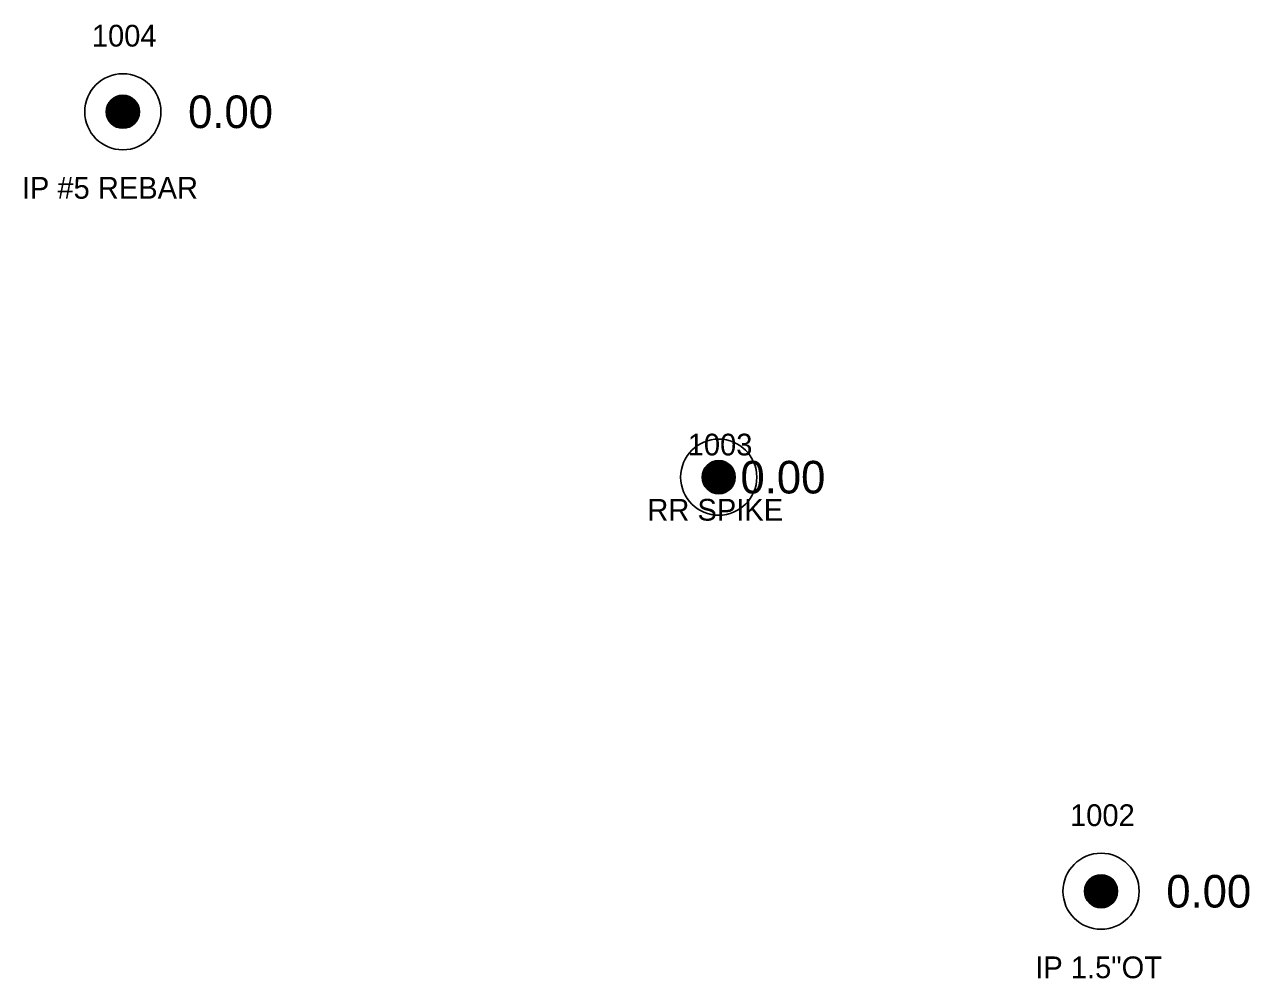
# Model space of a CAD drawing. Extents: x 1762456 to 1764480, y 822234 to 826541.
# Drawn here: x 1764423.2 to 1764479.5, y 825896.4 to 825940.3 of the extents above; entities that cross this region are included whole.
import ezdxf

# ---------------------------------------------------------------- set-up
doc = ezdxf.new("R2010")
doc.units = 0
for name, color, linetype in [('RD_EX_DV_Prop_txCode', 7, 'Continuous'), ('RD_EX_DV_PropPin', 7, 'Continuous'), ('RD_EX_TX_DV_Prop_ELEV', 7, 'Continuous'), ('RD_SMD_Locator', 7, 'Continuous')]:
    doc.layers.add(name, color=color, linetype=linetype)

msp = doc.modelspace()

# ---------------------------------------------------------------- linework, layer by layer
at = {"layer": 'RD_EX_DV_PropPin'}
for p, q in [((1764427.017, 825935.977), (1764427.017, 825936.573)), ((1764427.052, 825935.906), (1764427.052, 825936.645)), ((1764427.087, 825935.849), (1764427.087, 825936.702)), ((1764427.122, 825935.801), (1764427.122, 825936.749)), ((1764427.157, 825935.76), (1764427.157, 825936.79)), ((1764427.192, 825935.725), (1764427.192, 825936.826)), ((1764427.227, 825935.693), (1764427.227, 825936.857)), ((1764427.262, 825935.665), (1764427.262, 825936.885)), ((1764427.297, 825935.641), (1764427.297, 825936.91)), ((1764427.332, 825935.619), (1764427.332, 825936.932)), ((1764427.367, 825935.6), (1764427.367, 825936.951)), ((1764427.402, 825935.583), (1764427.402, 825936.968)), ((1764427.437, 825935.568), (1764427.437, 825936.983)), ((1764427.472, 825935.555), (1764427.472, 825936.996)), ((1764427.507, 825935.544), (1764427.507, 825937.007)), ((1764427.542, 825935.535), (1764427.542, 825937.016)), ((1764427.577, 825935.527), (1764427.577, 825937.023)), ((1764427.612, 825935.522), (1764427.612, 825937.029)), ((1764427.647, 825935.518), (1764427.647, 825937.033)), ((1764427.682, 825935.515), (1764427.682, 825937.036)), ((1764427.717, 825935.514), (1764427.717, 825937.036)), ((1764427.752, 825935.515), (1764427.752, 825937.036)), ((1764427.787, 825935.518), (1764427.787, 825937.033)), ((1764427.822, 825935.522), (1764427.822, 825937.029)), ((1764427.857, 825935.527), (1764427.857, 825937.023)), ((1764427.892, 825935.535), (1764427.892, 825937.016)), ((1764427.927, 825935.544), (1764427.927, 825937.007)), ((1764427.962, 825935.555), (1764427.962, 825936.996)), ((1764427.997, 825935.568), (1764427.997, 825936.983)), ((1764428.032, 825935.583), (1764428.032, 825936.968)), ((1764428.067, 825935.6), (1764428.067, 825936.951)), ((1764428.102, 825935.619), (1764428.102, 825936.932)), ((1764428.137, 825935.641), (1764428.137, 825936.91)), ((1764428.172, 825935.665), (1764428.172, 825936.885)), ((1764428.207, 825935.693), (1764428.207, 825936.857)), ((1764428.242, 825935.725), (1764428.242, 825936.826)), ((1764428.278, 825935.76), (1764428.278, 825936.79)), ((1764428.313, 825935.801), (1764428.313, 825936.749)), ((1764428.348, 825935.849), (1764428.348, 825936.702)), ((1764428.383, 825935.906), (1764428.383, 825936.645)), ((1764428.418, 825935.977), (1764428.418, 825936.573)), ((1764426.982, 825936.079), (1764426.982, 825936.471)), ((1764428.453, 825936.079), (1764428.453, 825936.471)), ((1764454.799, 825918.773), (1764454.799, 825920.159)), ((1764454.834, 825918.758), (1764454.834, 825920.173)), ((1764454.869, 825918.745), (1764454.869, 825920.186)), ((1764454.904, 825918.734), (1764454.904, 825920.197)), ((1764454.939, 825918.725), (1764454.939, 825920.207)), ((1764454.974, 825918.718), (1764454.974, 825920.214)), ((1764455.009, 825918.712), (1764455.009, 825920.22)), ((1764455.044, 825918.708), (1764455.044, 825920.224)), ((1764455.079, 825918.706), (1764455.079, 825920.226)), ((1764455.114, 825918.705), (1764455.114, 825920.227)), ((1764455.149, 825918.706), (1764455.149, 825920.226)), ((1764455.184, 825918.708), (1764455.184, 825920.224)), ((1764455.219, 825918.712), (1764455.219, 825920.22)), ((1764455.254, 825918.718), (1764455.254, 825920.214)), ((1764455.289, 825918.725), (1764455.289, 825920.207)), ((1764455.324, 825918.734), (1764455.324, 825920.197)), ((1764455.359, 825918.745), (1764455.359, 825920.186)), ((1764455.394, 825918.758), (1764455.394, 825920.173)), ((1764455.429, 825918.773), (1764455.429, 825920.159)), ((1764454.379, 825919.27), (1764454.379, 825919.662)), ((1764454.414, 825919.168), (1764454.414, 825919.764)), ((1764454.449, 825919.096), (1764454.449, 825919.835)), ((1764454.484, 825919.039), (1764454.484, 825919.892)), ((1764454.519, 825918.992), (1764454.519, 825919.94)), ((1764454.554, 825918.951), (1764454.554, 825919.981)), ((1764454.589, 825918.915), (1764454.589, 825920.017)), ((1764454.624, 825918.884), (1764454.624, 825920.048)), ((1764454.659, 825918.856), (1764454.659, 825920.076)), ((1764454.694, 825918.831), (1764454.694, 825920.1)), ((1764454.729, 825918.81), (1764454.729, 825920.122)), ((1764454.764, 825918.79), (1764454.764, 825920.142)), ((1764455.464, 825918.79), (1764455.464, 825920.142)), ((1764455.499, 825918.81), (1764455.499, 825920.122)), ((1764455.534, 825918.831), (1764455.534, 825920.1)), ((1764455.569, 825918.856), (1764455.569, 825920.076)), ((1764455.604, 825918.884), (1764455.604, 825920.048)), ((1764455.639, 825918.915), (1764455.639, 825920.017)), ((1764455.674, 825918.951), (1764455.674, 825919.981)), ((1764455.709, 825918.992), (1764455.709, 825919.94)), ((1764455.744, 825919.039), (1764455.744, 825919.892)), ((1764455.779, 825919.096), (1764455.779, 825919.835)), ((1764455.814, 825919.168), (1764455.814, 825919.764)), ((1764455.849, 825919.27), (1764455.849, 825919.662)), ((1764472.238, 825899.808), (1764472.238, 825901.027)), ((1764472.273, 825899.783), (1764472.273, 825901.052)), ((1764472.308, 825899.761), (1764472.308, 825901.074)), ((1764472.343, 825899.742), (1764472.343, 825901.093)), ((1764472.378, 825899.725), (1764472.378, 825901.11)), ((1764472.413, 825899.71), (1764472.413, 825901.125)), ((1764472.448, 825899.697), (1764472.448, 825901.138)), ((1764472.483, 825899.686), (1764472.483, 825901.149)), ((1764472.518, 825899.677), (1764472.518, 825901.158)), ((1764472.553, 825899.669), (1764472.553, 825901.165)), ((1764472.588, 825899.664), (1764472.588, 825901.171)), ((1764472.623, 825899.66), (1764472.623, 825901.175)), ((1764472.658, 825899.657), (1764472.658, 825901.178)), ((1764472.693, 825899.656), (1764472.693, 825901.178)), ((1764472.728, 825899.657), (1764472.728, 825901.178)), ((1764472.763, 825899.66), (1764472.763, 825901.175)), ((1764472.798, 825899.664), (1764472.798, 825901.171)), ((1764472.833, 825899.669), (1764472.833, 825901.165)), ((1764472.868, 825899.677), (1764472.868, 825901.158)), ((1764472.903, 825899.686), (1764472.903, 825901.149)), ((1764472.938, 825899.697), (1764472.938, 825901.138)), ((1764472.973, 825899.71), (1764472.973, 825901.125)), ((1764473.008, 825899.725), (1764473.008, 825901.11)), ((1764473.043, 825899.742), (1764473.043, 825901.093)), ((1764473.078, 825899.761), (1764473.078, 825901.074)), ((1764473.113, 825899.783), (1764473.113, 825901.052)), ((1764473.148, 825899.808), (1764473.148, 825901.027)), ((1764471.958, 825900.221), (1764471.958, 825900.614)), ((1764471.993, 825900.119), (1764471.993, 825900.715)), ((1764472.028, 825900.048), (1764472.028, 825900.787)), ((1764472.063, 825899.991), (1764472.063, 825900.844)), ((1764472.098, 825899.943), (1764472.098, 825900.892)), ((1764472.133, 825899.902), (1764472.133, 825900.932)), ((1764472.168, 825899.867), (1764472.168, 825900.968)), ((1764472.203, 825899.835), (1764472.203, 825901)), ((1764473.183, 825899.835), (1764473.183, 825901)), ((1764473.218, 825899.867), (1764473.218, 825900.968)), ((1764473.253, 825899.902), (1764473.253, 825900.932)), ((1764473.288, 825899.943), (1764473.288, 825900.892)), ((1764473.323, 825899.991), (1764473.323, 825900.844)), ((1764473.358, 825900.048), (1764473.358, 825900.787)), ((1764473.393, 825900.119), (1764473.393, 825900.715)), ((1764473.428, 825900.221), (1764473.428, 825900.614))]:
    msp.add_line(p, q, dxfattribs=at)
for centre, radius in [((1764427.717, 825936.275), 1.75), ((1764427.717, 825936.275), 0.761), ((1764455.114, 825919.466), 1.75), ((1764455.114, 825919.466), 0.761), ((1764472.693, 825900.417), 1.75), ((1764472.693, 825900.417), 0.761)]:
    msp.add_circle(centre, radius, dxfattribs=at)
at = {"layer": 'RD_SMD_Locator'}
for centre in [(1764427.717, 825936.275), (1764455.114, 825919.466), (1764455.114, 825919.466), (1764472.693, 825900.417)]:
    msp.add_circle(centre, 0.15, dxfattribs=at)

# ---------------------------------------------------------------- texts
at = {"layer": 'RD_EX_DV_Prop_txCode'}
for s, p in [('1004', (1764426.292, 825939.275)), ('IP #5 REBAR', (1764423.072, 825932.275)), ('1003', (1764453.689, 825920.466)), ('RR SPIKE', (1764451.834, 825917.466)), ('1002', (1764471.268, 825903.417)), ('IP 1.5"OT', (1764469.669, 825896.417))]:
    msp.add_text(s, height=1, dxfattribs=at).set_placement(p)
at = {"layer": 'RD_EX_TX_DV_Prop_ELEV'}
for p in [(1764430.717, 825935.525), (1764456.114, 825918.716), (1764475.693, 825899.667)]:
    msp.add_text('0.00', height=1.5, dxfattribs=at).set_placement(p)

doc.saveas('drawing.dxf')
